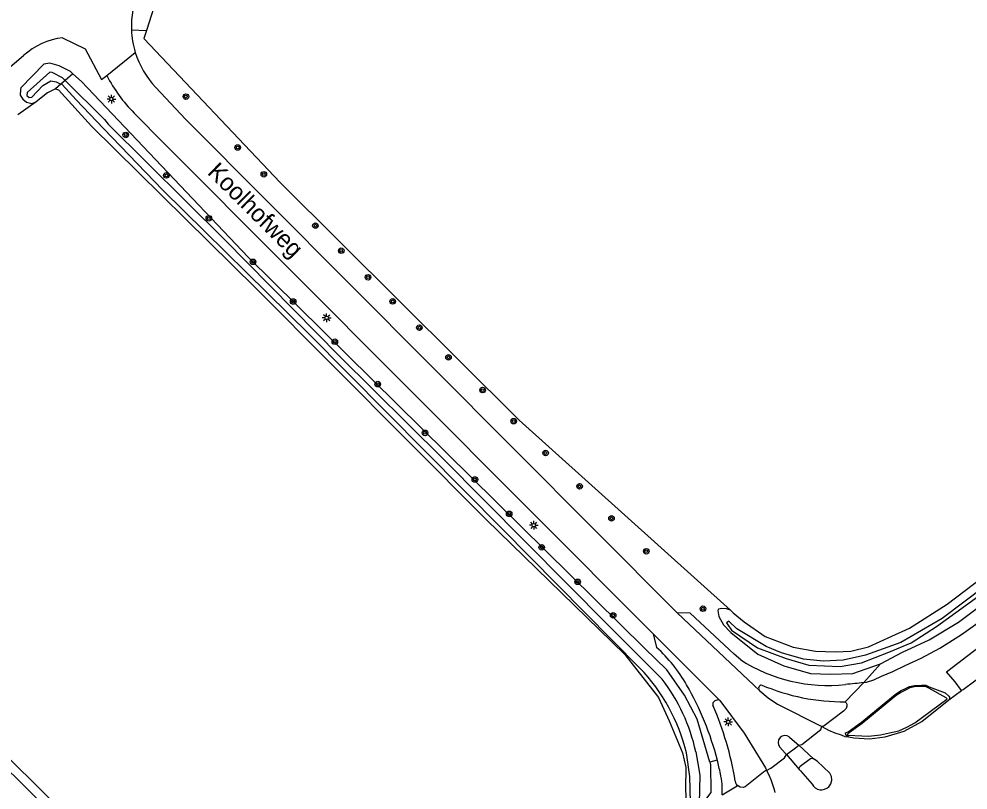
# Model space of a CAD drawing. Extents: x 141000 to 143000, y 400580 to 403500.
# Drawn here: x 142326.5 to 142462.9, y 402788.9 to 402899.7 of the extents above; entities that cross this region are included whole.
import ezdxf

# ---------------------------------------------------------------- set-up
doc = ezdxf.new("R2010")
doc.units = 0
for name, color, linetype in [('gg-anno-openbare ruimte label', 7, 'Continuous'), ('gg-knt-bronhoudergrens', 7, 'Continuous'), ('gg-knt-verharding', 7, 'Continuous'), ('gg-kntw-bovenkant insteek waterloop', 7, 'Continuous'), ('gg-kntw-waterlijn', 7, 'Continuous'), ('gt-grn-groengrens', 7, 'Continuous'), ('gt-grn-vlakafsluiter', 7, 'Continuous'), ('gt-grn-weggrens', 7, 'Continuous'), ('gt-symb-boom', 7, 'Continuous'), ('gt-symb-lichtmast', 7, 'Continuous'), ('gx-grn-maaiveld', 7, 'Continuous')]:
    doc.layers.add(name, color=color, linetype=linetype)

# ---------------------------------------------------------------- blocks, each defined once
blk = doc.blocks.new('gt0-LMAST')
at = {"layer": 'gt-symb-lichtmast'}
for p, q in [((-0.18, 0.17), (-0.45, 0.44)), ((-0.01, 0.25), (-0.01, 0.62)), ((0.17, 0.17), (0.44, 0.44)), ((-0.26, 0), (-0.63, 0)), ((-0.18, -0.18), (-0.45, -0.45)), ((-0.01, -0.25), (-0.01, -0.63)), ((0.44, -0.45), (0.17, -0.18)), ((0.24, 0), (0.62, 0))]:
    blk.add_line(p, q, dxfattribs=at)
blk.add_circle((-0.01, 0), 0.25, dxfattribs=at)
blk = doc.blocks.new('gt0-BOOM')
at = {"layer": 'gt-symb-boom'}
for radius in [0.4, 0.2]:
    blk.add_circle((0, 0), radius, dxfattribs=at)

msp = doc.modelspace()

# ---------------------------------------------------------------- linework, layer by layer
at = {"layer": 'gg-knt-bronhoudergrens'}
msp.add_line((142328.97, 402887.85), (142326.36, 402885.95), dxfattribs=at)
for points in [[(142348.57, 402904.35), (142345.91, 402901.41), (142344.83, 402898.08)], [(142344.83, 402898.08), (142344.46, 402896.95), (142364.06, 402876.23), (142398.39, 402842.08), (142428.79, 402814.76)], [(142368.96, 402748.16), (142369.92, 402749.18), (142351.54, 402767.36), (142280.62, 402837.33), (142279.39, 402836.06)]]:
    msp.add_lwpolyline(points, dxfattribs=at)
at = {"layer": 'gg-knt-verharding'}
for p, q in [((142324.59, 402892.27), (142327.18, 402894.49)), ((142432.97, 402803.18), (142421.09, 402814.38)), ((142417.68, 402811.36), (142427.23, 402801.77)), ((142417.68, 402811.36), (142418.16, 402809.4)), ((142460.17, 402801.86), (142461.98, 402803.24)), ((142438.62, 402795.35), (142440.72, 402793.42)), ((142436.81, 402794.03), (142438.64, 402791.88)), ((142427.57, 402788.22), (142429.75, 402789.53))]:
    msp.add_line(p, q, dxfattribs=at)
for points in [[(142715.38, 402998.49), (142700.67, 402987.25), (142696.38, 402983.7), (142693.54, 402981.02), (142685.05, 402972.24), (142683.81, 402971.03), (142681.77, 402969.39), (142656.16, 402949.41), (142634.11, 402932.25), (142619.29, 402920.83), (142590.85, 402898.68), (142557.42, 402872.77), (142535.96, 402856.17), (142533.15, 402854.17), (142522.24, 402847.83), (142514.23, 402843.16), (142508.05, 402838.65), (142483.27, 402819.56), (142467.25, 402807.04), (142462.21, 402803.3), (142461.98, 402803.24)], [(142332.79, 402897.05), (142336.02, 402895.44), (142338.37, 402891.05), (142339.15, 402891.61)], [(142421.09, 402814.38), (142350.49, 402885.3), (142346.15, 402889.93)], [(142417.68, 402811.36), (142347.37, 402881.82), (142343.08, 402886.22)], [(142461.98, 402803.24), (142461.05, 402804.46), (142459.81, 402805.92), (142475.54, 402817.94), (142490.74, 402829.68), (142509.46, 402844.02), (142511.98, 402845.85), (142513.22, 402846.7), (142513.86, 402847.16), (142515.08, 402847.71), (142518, 402849.07), (142521.47, 402850.72), (142524.02, 402852.11), (142525.52, 402853.13), (142527.11, 402854.35), (142529.3, 402856.14)], [(142430.24, 402807.64), (142429.3, 402808.45), (142422.98, 402814.36), (142421.09, 402814.38)], [(142447.95, 402804.36), (142448.31, 402804.41), (142449.38, 402804.78), (142450.48, 402805.27), (142452.13, 402805.94), (142453.86, 402806.82), (142456.16, 402807.87), (142458.84, 402809.32), (142461.98, 402811.28), (142466.85, 402814.77)], [(142432.97, 402803.18), (142434.2, 402802.16), (142435.52, 402801.27), (142441.88, 402798.06)], [(142445.73, 402796.57), (142445.37, 402796.8), (142445.31, 402797.16), (142445.7, 402797.28), (142447.6, 402798.66), (142452.45, 402802.65), (142453.23, 402803.17), (142453.93, 402803.52), (142454.51, 402803.8), (142455.2, 402803.94), (142456.23, 402804), (142456.85, 402803.98), (142457.35, 402803.75), (142459.62, 402802.89), (142460.16, 402802.42), (142460.24, 402802.27), (142460.25, 402802.1), (142460.24, 402802.02), (142460.21, 402801.93), (142460.17, 402801.86)], [(142427.23, 402801.77), (142427.02, 402801.88), (142426.8, 402801.84), (142426.51, 402801.72), (142426.26, 402801.46), (142426.24, 402801.11)], [(142427.23, 402801.77), (142430.75, 402797.09), (142433.83, 402792.09), (142433.95, 402791.73)], [(142445.28, 402801.61), (142445.42, 402801.44), (142445.49, 402801.24), (142445.5, 402800.97), (142445.4, 402800.65), (142445.01, 402800.25), (142442.25, 402798.15), (142442.03, 402798.05), (142441.88, 402798.06)], [(142445.73, 402796.57), (142446.49, 402796.41), (142448.77, 402796.3), (142451.03, 402796.57), (142453.76, 402797.4), (142456.27, 402798.77), (142460.17, 402801.86)], [(142441.88, 402798.06), (142442.88, 402797.54), (142443.79, 402797.15), (142444.69, 402796.84), (142445.21, 402796.61), (142445.73, 402796.57)], [(142437.25, 402796.51), (142438.33, 402795.6), (142438.62, 402795.35)], [(142436.81, 402794.03), (142436.63, 402794.22), (142435.86, 402795.08)], [(142436.81, 402794.03), (142438.11, 402794.98), (142438.62, 402795.35)], [(142438.64, 402791.88), (142438.63, 402792.05), (142438.78, 402792.36), (142440.26, 402793.46), (142440.54, 402793.49), (142440.72, 402793.42)], [(142438.64, 402791.88), (142438.84, 402791.66), (142440.5, 402789.78), (142440.7, 402789.48), (142440.96, 402789.24), (142441.27, 402789.06), (142441.61, 402788.97), (142441.96, 402788.95), (142442.31, 402789.02), (142442.64, 402789.17), (142442.91, 402789.39), (142443.22, 402789.83), (142443.35, 402790.34), (142443.3, 402790.87), (142443.06, 402791.35), (142441.24, 402793.08), (142440.72, 402793.42)], [(142433.95, 402791.73), (142433.82, 402791.67), (142433.54, 402791.49), (142430.88, 402789.38), (142430.58, 402789.3), (142430.15, 402789.33), (142429.8, 402789.56), (142429.75, 402789.53)]]:
    msp.add_lwpolyline(points, dxfattribs=at)
for centre, radius, start, end in [((142355.52, 402898.73), 12.85, 131.9804, 182.5003), ((142334.15, 402886.68), 10.46, 97.4267, 131.7515), ((142355.5, 402898.72), 12.84, 182.4906, 197.1527), ((142355.51, 402898.72), 12.85, 197.1383, 223.2096), ((142357.54, 402900.87), 20.59, 206.7308, 225.3657), ((142403.79, 402793.45), 21.47, 29.5657, 47.9831), ((142442.79, 402827.11), 23.17, 237.2152, 276.2423), ((142468.9, 402589.64), 215.73, 95.5729, 96.2779), ((142385.15, 402782.53), 43.08, 14.3212, 29.9588), ((142433.31, 402803.53), 0.488, 97.2878, 225.5536), ((142444.98, 402831.42), 29.81, 246.8448, 270.5866), ((142384.6, 402782.92), 45.44, 9.2305, 23.6032), ((142436.61, 402795.75), 0.999, 49.5576, 221.8249), ((142384.59, 402782.42), 43.64, 11.6984, 14.2908), ((142418.08, 402788.99), 9.52, 355.3534, 13.8124), ((142430.49, 402790.26), 1.04, 182.8424, 224.3718)]:
    msp.add_arc(centre, radius, start, end, dxfattribs=at)
at = {"layer": 'gg-kntw-bovenkant insteek waterloop'}
for points in [[(142428.79, 402814.76), (142429.16, 402814.41), (142430.72, 402813.07), (142433.76, 402810.99), (142437.8, 402809.46), (142440.98, 402808.87), (142443.89, 402808.8), (142446.09, 402808.89), (142448.61, 402809.52), (142451.95, 402811.01), (142454.52, 402812.19), (142459.9, 402815.61), (142491.15, 402839.34), (142515.23, 402857.34), (142521.13, 402860.91), (142544.53, 402878.21), (142590.32, 402913.85), (142635.9, 402949.08), (142683.62, 402986.21), (142733.22, 403024.46), (142755.5, 403041.93)], [(142450.34, 402807.04), (142453.52, 402808.71), (142457.33, 402810.51), (142461.56, 402813.04), (142475.85, 402823.79), (142497.21, 402840.15), (142505.1, 402846.44), (142507.92, 402848.58), (142512.54, 402851.09), (142516.34, 402853.17), (142520.14, 402855.62), (142523.48, 402858.13), (142546.06, 402875.9), (142574.48, 402897.61), (142597.34, 402915.4), (142623.44, 402935.93), (142651.22, 402957.67), (142683.57, 402982.83), (142710.29, 403003.56)], [(142334.27, 402891.86), (142333.91, 402892.18), (142332.27, 402893), (142330.97, 402893.38), (142330.1, 402893.22), (142326.78, 402889.86), (142326.72, 402889.62), (142326.67, 402888.78), (142327.07, 402888.21), (142327.59, 402887.77), (142328.37, 402887.6), (142328.97, 402887.85)], [(142425.83, 402792.94), (142423.97, 402799.09), (142422.18, 402802.55), (142419.61, 402806.19), (142416.41, 402809.31), (142359.46, 402865.5), (142335.52, 402890.73), (142334.27, 402891.86)], [(142331.74, 402889.72), (142330.61, 402889.1), (142328.97, 402887.85)], [(142331.74, 402889.72), (142332.17, 402889.54), (142336.93, 402884.31), (142360.54, 402861.07), (142393.64, 402827.81), (142413.57, 402808.4), (142418.43, 402802.23), (142419.98, 402798.88), (142421.87, 402794.25), (142422.38, 402792.15), (142422.32, 402789.03), (142422.39, 402787.07), (142420.59, 402784.52), (142414.92, 402778.62), (142410.64, 402775.34), (142372.19, 402744.96)], [(142368.96, 402748.16), (142316.88, 402799.79), (142279.39, 402836.06)], [(142428.79, 402814.76), (142428.21, 402814.95), (142427.54, 402815.03), (142427.05, 402814.9), (142426.95, 402814.73), (142427.08, 402813.85), (142427.75, 402812.66), (142428.83, 402811.56), (142432.69, 402808.45), (142436.46, 402806.76), (142440.29, 402805.69), (142443.15, 402805.59), (142446.35, 402805.66), (142450.34, 402807.04)], [(142425.83, 402792.94), (142425.92, 402792.61), (142425.95, 402788.55), (142424.14, 402786.16)]]:
    msp.add_lwpolyline(points, dxfattribs=at)
at = {"layer": 'gg-kntw-waterlijn'}
for points in [[(142333.15, 402890.91), (142332.77, 402891.29), (142331.28, 402892.06), (142330.93, 402892.08), (142327.7, 402889.17), (142327.66, 402888.75), (142328, 402888.44), (142328.38, 402888.48), (142329.92, 402890.2), (142331.1, 402890.83), (142331.88, 402890.72), (142332.54, 402890.39)], [(142415.76, 402806.45), (142396.01, 402826.39), (142368.21, 402854.43), (142347.21, 402875.14), (142338.64, 402884.01), (142334.74, 402888.11), (142332.71, 402890.31), (142332.54, 402890.39)], [(142333.15, 402890.91), (142338.79, 402885.27), (142339.32, 402884.61), (142356.05, 402868.05), (142372.53, 402851.34), (142387.41, 402836.57), (142411.18, 402812.62), (142418.94, 402804.84)], [(142493.85, 402839.69), (142459.22, 402813.58), (142453.27, 402810.12), (142448.16, 402808.28), (142444.95, 402807.6), (142442.14, 402807.44), (142439.29, 402807.72), (142436.11, 402808.63), (142433.92, 402809.54), (142429.67, 402812.08), (142428.53, 402813.21), (142428.22, 402812.96), (142428.38, 402812.68), (142428.93, 402811.89), (142432.65, 402809.36), (142436.76, 402807.82), (142440.03, 402806.87), (142444.53, 402806.67), (142447.62, 402807.18), (142451.55, 402808.71), (142454.73, 402810.08), (142458.36, 402812.43), (142471.76, 402822.09)], [(142423.78, 402794.41), (142424.38, 402791.05), (142424.27, 402786.97), (142422.13, 402783.48), (142415.92, 402776.81), (142396.19, 402761.58), (142372.18, 402742.94), (142361.38, 402734.29), (142319.49, 402701.92), (142311.75, 402696.01)], [(142372.61, 402744.54), (142395.57, 402762.36), (142415.22, 402778.11), (142421.22, 402784.21), (142423.05, 402787.13), (142422.91, 402790.88), (142422.43, 402794.25)]]:
    msp.add_lwpolyline(points, dxfattribs=at)
for centre, radius, start, end in [((142396.52, 402787.99), 26.66, 13.5888, 43.8176), ((142398.5, 402789.01), 25.85, 12.0615, 37.7561)]:
    msp.add_arc(centre, radius, start, end, dxfattribs=at)
at = {"layer": 'gt-grn-groengrens'}
for p, q in [((142342.68, 402898.17), (142344.83, 402898.08)), ((142426.88, 402793.19), (142425.83, 402792.94))]:
    msp.add_line(p, q, dxfattribs=at)
at = {"layer": 'gt-grn-vlakafsluiter'}
for p, q in [((142334.27, 402891.86), (142333.15, 402890.91)), ((142332.54, 402890.39), (142331.74, 402889.72)), ((142333.15, 402890.91), (142332.54, 402890.39)), ((142447.95, 402804.36), (142450.34, 402807.04))]:
    msp.add_line(p, q, dxfattribs=at)
at = {"layer": 'gt-grn-weggrens'}
for p, q in [((142339.15, 402891.61), (142343.23, 402894.94)), ((142445.28, 402801.61), (142447.95, 402804.36))]:
    msp.add_line(p, q, dxfattribs=at)
for points in [[(142438.62, 402795.35), (142439.01, 402795.45), (142441.74, 402797.64), (142441.88, 402798.06)], [(142433.95, 402791.73), (142434.56, 402792.04), (142436.55, 402793.57), (142436.81, 402794.03)]]:
    msp.add_lwpolyline(points, dxfattribs=at)
at = {"layer": 'gx-grn-maaiveld'}
for points in [[(142456.23, 402803.8), (142455.22, 402803.74), (142454.57, 402803.61), (142454.02, 402803.34), (142453.33, 402803), (142452.57, 402802.49), (142447.72, 402798.5), (142445.83, 402797.12), (142445.61, 402796.93), (142445.6, 402796.86), (142445.61, 402796.85), (142445.71, 402796.81), (142448.61, 402796.68), (142450.32, 402796.87), (142451.63, 402797.14), (142452.96, 402797.45), (142454.13, 402797.94), (142455.27, 402798.58), (142459.88, 402801.98), (142459.92, 402802.05), (142459.75, 402802.17), (142457.26, 402803.57), (142456.8, 402803.78), (142456.23, 402803.8)], [(142433.95, 402791.73), (142434.26, 402791.19), (142434.56, 402790.41), (142435.04, 402789), (142435.14, 402788.58)]]:
    msp.add_lwpolyline(points, dxfattribs=at)

# ---------------------------------------------------------------- block references
at = {"layer": 'gt-symb-boom'}
for p in [(142350.51, 402888.58), (142341.86, 402883.07), (142357.95, 402881.27), (142347.7, 402877.26), (142361.71, 402877.42), (142353.8, 402871.1), (142369.12, 402870.03), (142372.83, 402866.43), (142360.16, 402864.84), (142376.68, 402862.62), (142365.92, 402859.14), (142380.23, 402859.15), (142384.06, 402855.37), (142371.91, 402853.35), (142388.25, 402851.11), (142378.08, 402847.26), (142393.15, 402846.4), (142397.62, 402841.94), (142384.87, 402840.25), (142402.2, 402837.36), (142392.04, 402833.55), (142407.09, 402832.57), (142396.97, 402828.62), (142411.67, 402827.97), (142401.64, 402823.8), (142416.67, 402823.24), (142406.8, 402818.84), (142424.82, 402814.98), (142411.92, 402814.03)]:
    msp.add_blockref('gt0-BOOM', p, dxfattribs=at)
at = {"layer": 'gt-symb-lichtmast'}
for p in [(142339.8, 402888.23), (142370.74, 402856.79), (142400.51, 402826.98), (142428.46, 402798.71)]:
    msp.add_blockref('gt0-LMAST', p, dxfattribs=at)

# ---------------------------------------------------------------- texts
at = {"layer": 'gg-anno-openbare ruimte label'}
msp.add_text('Koolhofweg', height=2.5, rotation=315.2, dxfattribs=at).set_placement((142353.45, 402877.56))

doc.saveas('drawing.dxf')
